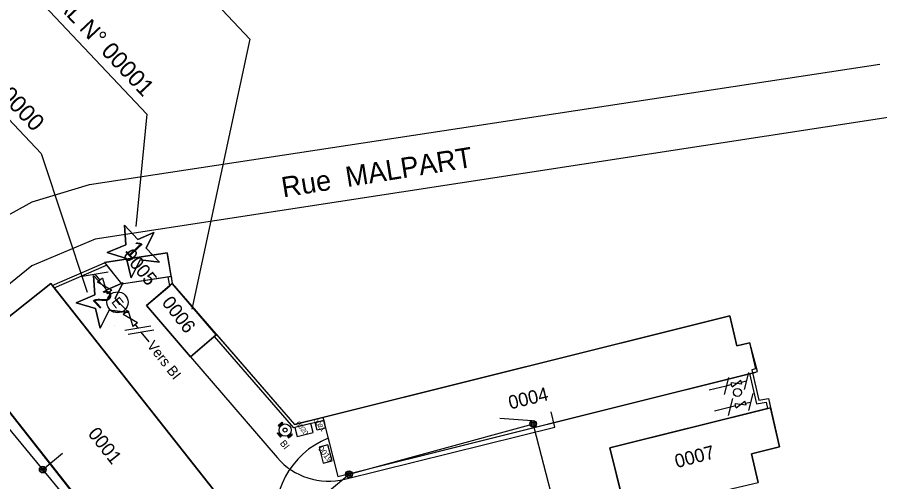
# Model space of a CAD drawing. Extents: x 703432 to 707394, y 7057985 to 7059523.
# Drawn here: x 704771.8 to 704899.3, y 7059327.9 to 7059396.7 of the extents above; entities that cross this region are included whole.
import ezdxf

# ---------------------------------------------------------------- set-up
doc = ezdxf.new("R2010")
doc.units = 0
for name, color, linetype in [('DH_HACHURE-MOTIF', 7, 'Continuous'), ('DH_TEXTE', 7, 'Continuous'), ('GEOSID_AIRE_AMENAGEE_NUMERO', 7, 'Continuous'), ('GEOSID_AIRE_AMENAGEE_POLYGONE', 7, 'Continuous'), ('GO_DALLE', 7, 'Continuous'), ('GO_MUR_EXTERIEUR', 7, 'Continuous'), ('IMM_LIMITE PHYSIQUE', 7, 'Continuous'), ('LIB_08', 7, 'Continuous'), ('R_PLU_CANALISATION_CL_A', 7, 'Continuous'), ('RES_BASSE TENSION AERIEN', 7, 'Continuous'), ('RES_CHAUFFAGE SECONDAIRE', 7, 'Continuous'), ('RES_EAU BASSE PRESSION', 7, 'Continuous'), ('RES_EAU BASSE PRESSION - EQUIP - TEXTE', 7, 'Continuous'), ('RES_INCENDIE - EQUIP - TEXTE', 7, 'Continuous'), ('SID_NUMERO_BATI', 7, 'Continuous'), ('SID_POLYLIGNES_BATI', 7, 'Continuous'), ('SID_POLYLIGNES_IMMEUBLE', 7, 'Continuous'), ('VOIRIE_ROUTE', 7, 'Continuous')]:
    doc.layers.add(name, color=color, linetype=linetype)

msp = doc.modelspace()

# ---------------------------------------------------------------- linework, layer by layer
at = {"layer": 'DH_HACHURE-MOTIF'}
for p, q in [((704790.92, 7059354), (704794.34, 7059356.93)), ((704794.34, 7059356.93), (704794.72, 7059357.25)), ((704794.72, 7059357.25), (704801.22, 7059349.66)), ((704797.42, 7059346.41), (704790.92, 7059354))]:
    msp.add_line(p, q, dxfattribs=at)
for points in [[(704794.09, 7059358.26), (704794.54, 7059358.33), (704793.96, 7059361.78), (704784.69, 7059360.35), (704785.02, 7059359.95), (704787.24, 7059357.23), (704794.09, 7059358.26)], [(704764.01, 7059346.61), (704766.21, 7059343.82), (704794.39, 7059308.1), (704800.87, 7059313.21), (704807.43, 7059318.38), (704806.81, 7059319.17), (704777.07, 7059356.86), (704776.77, 7059357.24), (704763.73, 7059346.96), (704764.01, 7059346.61)], [(704817.12, 7059337), (704817.4, 7059335.86), (704819.19, 7059328.7), (704880.85, 7059344.11), (704881.28, 7059344.22), (704880.13, 7059348.5), (704878.19, 7059348.01), (704877.16, 7059352.46), (704840.29, 7059343.25), (704817.01, 7059337.43), (704817.12, 7059337)], [(704801.22, 7059349.66), (704800.88, 7059349.36), (704797.42, 7059346.41)], [(704866.39, 7059325.41), (704866.63, 7059324.35), (704881.38, 7059327.83), (704880.38, 7059332.05), (704884.52, 7059333.08), (704883.19, 7059338.88), (704882.76, 7059338.77), (704859.41, 7059332.93), (704861.6, 7059324.2), (704866.39, 7059325.41)], [(704815.23, 7059336.52), (704812.85, 7059335.93), (704813.17, 7059334.64), (704815.55, 7059335.23), (704815.23, 7059336.52)], [(704817.06, 7059330.68), (704818.35, 7059331.01), (704817.75, 7059333.38), (704816.46, 7059333.06), (704817.06, 7059330.68)]]:
    msp.add_lwpolyline(points, dxfattribs=at)
at = {"layer": 'GEOSID_AIRE_AMENAGEE_POLYGONE'}
msp.add_lwpolyline([(704816.14, 7059335.54), (704815.86, 7059336.68), (704817.11, 7059337), (704817.4, 7059335.85)], close=True, dxfattribs=at)
at = {"layer": 'GO_DALLE'}
msp.add_lwpolyline([(704817.12, 7059337), (704817.4, 7059335.86), (704816.14, 7059335.54), (704815.86, 7059336.68)], close=True, dxfattribs=at)
at = {"layer": 'GO_MUR_EXTERIEUR'}
for p, q in [((704793.96, 7059361.78), (704784.69, 7059360.35)), ((704794.54, 7059358.33), (704793.96, 7059361.78)), ((704784.69, 7059360.35), (704787.24, 7059357.23)), ((704787.24, 7059357.23), (704794.54, 7059358.33)), ((704763.73, 7059346.96), (704776.77, 7059357.24)), ((704776.77, 7059357.24), (704807.43, 7059318.38)), ((704794.72, 7059357.25), (704790.92, 7059354)), ((704801.22, 7059349.66), (704794.72, 7059357.25)), ((704790.92, 7059354), (704797.42, 7059346.41)), ((704790.92, 7059354), (704790.92, 7059354)), ((704877.16, 7059352.46), (704817.01, 7059337.43)), ((704878.19, 7059348.01), (704877.16, 7059352.46)), ((704797.42, 7059346.41), (704801.22, 7059349.66)), ((704880.13, 7059348.5), (704878.19, 7059348.01)), ((704881.28, 7059344.22), (704880.13, 7059348.5)), ((704794.39, 7059308.1), (704763.73, 7059346.96)), ((704819.19, 7059328.7), (704881.28, 7059344.22)), ((704859.41, 7059332.93), (704883.19, 7059338.88)), ((704883.19, 7059338.88), (704884.52, 7059333.08)), ((704817.01, 7059337.43), (704819.19, 7059328.7)), ((704861.6, 7059324.2), (704859.41, 7059332.93)), ((704884.52, 7059333.08), (704880.38, 7059332.05)), ((704880.38, 7059332.05), (704881.38, 7059327.83))]:
    msp.add_line(p, q, dxfattribs=at)
for points in [[(704812.85, 7059335.93), (704813.17, 7059334.64), (704815.55, 7059335.23), (704815.23, 7059336.52)], [(704817.75, 7059333.38), (704816.46, 7059333.06), (704817.06, 7059330.68), (704818.35, 7059331.01)]]:
    msp.add_lwpolyline(points, close=True, dxfattribs=at)
at = {"layer": 'IMM_LIMITE PHYSIQUE'}
for p, q in [((704776.98, 7059356.98), (704784.71, 7059360.31)), ((704777.28, 7059356.62), (704785.02, 7059359.96)), ((704794.09, 7059358.26), (704794.32, 7059356.91)), ((704794.54, 7059358.33), (704794.72, 7059357.25)), ((704800.93, 7059349.41), (704812.67, 7059335.88)), ((704801.27, 7059349.7), (704812.82, 7059336.38)), ((704817.01, 7059337.43), (704812.82, 7059336.38)), ((704817.13, 7059337), (704812.67, 7059335.88)), ((704884.04, 7059333.58), (704884.04, 7059333.58))]:
    msp.add_line(p, q, dxfattribs=at)
for points in [[(704880.09, 7059343.93), (704881.14, 7059339.45), (704882.54, 7059339.72), (704882.75, 7059338.77)], [(704880.53, 7059344.03), (704881.48, 7059339.97), (704882.88, 7059340.24), (704883.19, 7059338.88)]]:
    msp.add_lwpolyline(points, dxfattribs=at)
at = {"layer": 'LIB_08'}
for p, q in [((704789.64, 7059363.78), (704787.67, 7059365.87)), ((704787.67, 7059365.87), (704787.84, 7059363)), ((704792.01, 7059364.8), (704789.64, 7059363.78)), ((704790.85, 7059362.5), (704792.01, 7059364.8)), ((704787.84, 7059363), (704785.12, 7059361.83)), ((704792.82, 7059360.41), (704790.85, 7059362.5)), ((704788.64, 7059358.1), (704789.97, 7059360.74)), ((704789.97, 7059360.74), (704792.82, 7059360.41)), ((704785.05, 7059356.34), (704783.08, 7059358.43)), ((704783.08, 7059358.43), (704783.25, 7059355.57)), ((704787.41, 7059357.36), (704785.05, 7059356.34)), ((704786.26, 7059355.06), (704787.41, 7059357.36)), ((704783.25, 7059355.57), (704780.53, 7059354.39)), ((704788.23, 7059352.97), (704786.26, 7059355.06)), ((704784.05, 7059350.66), (704785.38, 7059353.31)), ((704785.38, 7059353.31), (704788.23, 7059352.97))]:
    msp.add_line(p, q, dxfattribs=at)
for points in [[(704767.68, 7059434.23), (704806.21, 7059393.39), (704797.62, 7059353.45)], [(704752.82, 7059422.73), (704790.94, 7059382.33), (704789.35, 7059365.71)], [(704733.91, 7059420.43), (704775.36, 7059376.5), (704782.12, 7059355.95)], [(704785.12, 7059361.83), (704787.96, 7059360.98), (704787.96, 7059360.98)], [(704787.96, 7059360.98), (704787.96, 7059360.98), (704788.64, 7059358.1)], [(704780.53, 7059354.39), (704783.36, 7059353.54), (704783.37, 7059353.54)], [(704783.37, 7059353.54), (704783.36, 7059353.54), (704784.05, 7059350.66)]]:
    msp.add_lwpolyline(points, dxfattribs=at)
for points in [[(704787.67, 7059365.87), (704789.65, 7059363.78), (704792.01, 7059364.8), (704790.85, 7059362.5), (704792.82, 7059360.41), (704789.97, 7059360.74), (704788.64, 7059358.1), (704787.96, 7059360.98), (704785.12, 7059361.83), (704787.84, 7059363)], [(704783.08, 7059358.43), (704785.05, 7059356.34), (704787.41, 7059357.36), (704786.26, 7059355.06), (704788.23, 7059352.97), (704785.38, 7059353.31), (704784.05, 7059350.66), (704783.36, 7059353.54), (704780.53, 7059354.39), (704783.25, 7059355.57)]]:
    msp.add_lwpolyline(points, close=True, dxfattribs=at)
at = {"layer": 'R_PLU_CANALISATION_CL_A'}
msp.add_circle((704878.3, 7059341.14), 0.6, dxfattribs=at)
at = {"layer": 'RES_BASSE TENSION AERIEN'}
msp.add_line((704797.42, 7059346.41), (704810.24, 7059331.49), dxfattribs=at)
msp.add_lwpolyline([(704820.24, 7059328.3), (704851.28, 7059336.02), (704850.74, 7059338.26)], dxfattribs=at)
msp.add_arc((704817.83, 7059338.01), 10, 220.6803, 283.9557, dxfattribs=at)
at = {"layer": 'RES_CHAUFFAGE SECONDAIRE'}
msp.add_arc((704822.5, 7059322.74), 12.55, 112.1042, 191.7308, dxfattribs=at)
at = {"layer": 'RES_EAU BASSE PRESSION'}
for p, q in [((704762.6, 7059345.41), (704794.07, 7059307.33)), ((704879.94, 7059344.09), (704879.3, 7059341.58)), ((704877.42, 7059342.29), (704876.65, 7059342.09)), ((704880.56, 7059340.98), (704879.92, 7059338.47)), ((704878.04, 7059339.17), (704877.26, 7059338.98)), ((704843.14, 7059337.32), (704847.96, 7059336.97)), ((704820.86, 7059329.03), (704847.6, 7059336.36)), ((704848.21, 7059336.01), (704855.35, 7059308.06)), ((704775.57, 7059329.72), (704778.49, 7059332.13)), ((704811.85, 7059321.58), (704820.86, 7059329.03))]:
    msp.add_line(p, q, dxfattribs=at)
at = {"layer": 'RES_EAU BASSE PRESSION - EQUIP - TEXTE'}
for p, q in [((704877.5, 7059341.99), (704877.35, 7059342.58)), ((704878.95, 7059342.36), (704877.35, 7059342.58)), ((704877.5, 7059341.99), (704878.81, 7059342.94)), ((704878.95, 7059342.36), (704878.81, 7059342.94)), ((704878.88, 7059342.65), (704879.62, 7059342.84)), ((704876.65, 7059342.09), (704874.12, 7059341.46)), ((704877.26, 7059338.98), (704874.89, 7059338.38)), ((704878.11, 7059338.88), (704877.97, 7059339.46)), ((704879.57, 7059339.24), (704877.97, 7059339.46)), ((704878.11, 7059338.88), (704879.42, 7059339.83)), ((704879.57, 7059339.24), (704879.42, 7059339.83)), ((704879.49, 7059339.54), (704880.24, 7059339.72))]:
    msp.add_line(p, q, dxfattribs=at)
for centre, radius in [((704848.09, 7059336.49), 0.5), ((704848.09, 7059336.49), 0.45), ((704848.09, 7059336.49), 0.25), ((704848.09, 7059336.49), 0.05), ((704775.57, 7059329.72), 0.5), ((704775.57, 7059329.72), 0.45), ((704775.57, 7059329.72), 0.25), ((704775.57, 7059329.72), 0.05), ((704820.86, 7059329.03), 0.5), ((704820.86, 7059329.03), 0.45), ((704820.86, 7059329.03), 0.25), ((704820.86, 7059329.03), 0.05)]:
    msp.add_circle(centre, radius, dxfattribs=at)
at = {"layer": 'RES_INCENDIE - EQUIP - TEXTE'}
for p, q in [((704781.41, 7059358.32), (704785.23, 7059358.99)), ((704784.04, 7059357.75), (704783.32, 7059358.66)), ((704784.39, 7059358.03), (704783.68, 7059357.47)), ((704784.39, 7059358.03), (704785.08, 7059355.71)), ((704785.78, 7059356.26), (704783.68, 7059357.47)), ((704785.78, 7059356.26), (704785.08, 7059355.71)), ((704785.43, 7059355.99), (704785.66, 7059355.69)), ((704788.18, 7059353.23), (704787.47, 7059352.67)), ((704789.57, 7059351.46), (704787.47, 7059352.67)), ((704787.83, 7059352.95), (704787.59, 7059353.24)), ((704788.18, 7059353.23), (704788.87, 7059350.9)), ((704789.57, 7059351.46), (704788.87, 7059350.9)), ((704786.11, 7059351.04), (704786.11, 7059351.04)), ((704787.72, 7059350.33), (704791.54, 7059351)), ((704788.18, 7059349.74), (704792, 7059350.42)), ((704789.22, 7059351.18), (704789.63, 7059350.67)), ((704790.09, 7059350.08), (704791.25, 7059348.61)), ((704876.96, 7059343.35), (704876.33, 7059340.84)), ((704877.58, 7059340.23), (704876.95, 7059337.72)), ((704810.38, 7059336.27), (704810.93, 7059336.73)), ((704810.38, 7059336.27), (704810.47, 7059336.16)), ((704810.47, 7059336.16), (704811.03, 7059336.61)), ((704810.52, 7059336.19), (704810.65, 7059336.04)), ((704810.93, 7059336.73), (704811.03, 7059336.61)), ((704810.98, 7059336.57), (704811.11, 7059336.42)), ((704810.26, 7059335.09), (704810.37, 7059335.18)), ((704810.26, 7059335.09), (704810.71, 7059334.53)), ((704810.37, 7059335.18), (704810.83, 7059334.63)), ((704810.41, 7059335.14), (704810.57, 7059335.27)), ((704810.79, 7059334.67), (704810.95, 7059334.8)), ((704811.8, 7059334.53), (704812.36, 7059334.99)), ((704811.9, 7059334.42), (704812.45, 7059334.87)), ((704812.18, 7059335.11), (704812.31, 7059334.95)), ((704812.36, 7059334.99), (704812.45, 7059334.87)), ((704810.71, 7059334.53), (704810.83, 7059334.63)), ((704811.72, 7059334.73), (704811.85, 7059334.57)), ((704811.8, 7059334.53), (704811.9, 7059334.42))]:
    msp.add_line(p, q, dxfattribs=at)
for centre, radius in [((704786.63, 7059354.47), 1.56), ((704811.41, 7059335.57), 0.9), ((704811.41, 7059335.57), 0.3)]:
    msp.add_circle(centre, radius, dxfattribs=at)
at = {"layer": 'SID_POLYLIGNES_BATI'}
for p, q in [((704793.96, 7059361.78), (704784.69, 7059360.35)), ((704794.54, 7059358.33), (704793.96, 7059361.78)), ((704784.69, 7059360.35), (704787.24, 7059357.23)), ((704787.24, 7059357.23), (704794.54, 7059358.33)), ((704763.73, 7059346.96), (704776.77, 7059357.24)), ((704776.77, 7059357.24), (704807.43, 7059318.38)), ((704794.72, 7059357.25), (704790.92, 7059354)), ((704801.22, 7059349.66), (704794.72, 7059357.25)), ((704790.92, 7059354), (704797.42, 7059346.41)), ((704790.92, 7059354), (704790.92, 7059354)), ((704877.16, 7059352.46), (704817.01, 7059337.43)), ((704878.19, 7059348.01), (704877.16, 7059352.46)), ((704797.42, 7059346.41), (704801.22, 7059349.66)), ((704880.13, 7059348.5), (704878.19, 7059348.01)), ((704881.28, 7059344.22), (704880.13, 7059348.5)), ((704794.39, 7059308.1), (704763.73, 7059346.96)), ((704819.19, 7059328.7), (704881.28, 7059344.22)), ((704817.01, 7059337.43), (704819.19, 7059328.7))]:
    msp.add_line(p, q, dxfattribs=at)
for points in [[(704812.85, 7059335.93), (704813.17, 7059334.64), (704815.55, 7059335.23), (704815.23, 7059336.52)], [(704816.14, 7059335.54), (704815.86, 7059336.68), (704817.12, 7059337), (704817.4, 7059335.86)], [(704817.75, 7059333.38), (704816.46, 7059333.06), (704817.06, 7059330.68), (704818.35, 7059331.01)]]:
    msp.add_lwpolyline(points, close=True, dxfattribs=at)
at = {"layer": 'SID_POLYLIGNES_IMMEUBLE'}
for p, q in [((704812.82, 7059336.38), (704877.16, 7059352.46)), ((704877.16, 7059352.46), (704878.19, 7059348.01)), ((704878.19, 7059348.01), (704880.09, 7059348.49)), ((704812.82, 7059336.38), (704812.82, 7059336.38)), ((704884.52, 7059333.08), (704880.38, 7059332.05)), ((704880.38, 7059332.05), (704881.38, 7059327.83))]:
    msp.add_line(p, q, dxfattribs=at)
for points in [[(704776.77, 7059357.24), (704776.98, 7059356.98), (704784.71, 7059360.31), (704784.69, 7059360.35), (704793.96, 7059361.78)], [(704793.96, 7059361.78), (704794.72, 7059357.25), (704812.82, 7059336.38)], [(704748.31, 7059333.98), (704763.73, 7059346.96), (704776.77, 7059357.24)], [(704880.09, 7059348.49), (704880.99, 7059344.65), (704880.42, 7059344.5), (704881.48, 7059339.97), (704882.88, 7059340.24), (704884.52, 7059333.08)]]:
    msp.add_lwpolyline(points, dxfattribs=at)
at = {"layer": 'VOIRIE_ROUTE'}
for points in [[(704740.74, 7059343.69), (704767.97, 7059366.05), (704774, 7059369.35), (704782.46, 7059371.89), (704899.35, 7059389.72)], [(704900.6, 7059381.84), (704783.31, 7059363.81), (704773.95, 7059359.85), (704746.36, 7059337.47)]]:
    msp.add_lwpolyline(points, dxfattribs=at)

# ---------------------------------------------------------------- texts
at = {"layer": 'DH_TEXTE'}
msp.add_text('Rue  MALPART', height=3, rotation=9.1668, dxfattribs=at).set_placement((704811.13, 7059369.98))
at = {"layer": 'GEOSID_AIRE_AMENAGEE_NUMERO'}
msp.add_text('0021', height=0.225, rotation=8.0308, dxfattribs=at).set_placement((704816.22, 7059336.18))
at = {"layer": 'LIB_08'}
for s, height, rotation, p in [('30000110341129_LOCAL N° 00001', 2.5, 313.3307, (704753.56, 7059423.84)), ('40626.548.0730.05_N° LOCAL 00000', 2.5, 313.9654, (704735, 7059420.29)), ('1', 2.65, 313.3307, (704787.59, 7059362.09)), ('2', 2.65, 313.3307, (704782.83, 7059354.83))]:
    msp.add_text(s, height=height, rotation=rotation, dxfattribs=at).set_placement(p)
at = {"layer": 'RES_EAU BASSE PRESSION - EQUIP - TEXTE'}
msp.add_text('Vers réseau eau', height=1.5, rotation=308.2727, dxfattribs=at).set_placement((704763.94, 7059330.84))
at = {"layer": 'RES_INCENDIE - EQUIP - TEXTE'}
for s, height, p in [('E', 1.5, (704785.64, 7059354.51)), ('Vers BI', 1.5, (704790.9, 7059348.05)), ('BI', 1, (704810.58, 7059333.6))]:
    msp.add_text(s, height=height, rotation=308.2727, dxfattribs=at).set_placement(p)
at = {"layer": 'SID_NUMERO_BATI'}
for s, height, rotation, p in [('0005', 2, 309.3307, (704787.32, 7059361.37)), ('0006', 2, 307.9879, (704793.08, 7059354.4)), ('0004', 2, 13.5243, (704844.7, 7059338.62)), ('0021', 0.702, 308.0308, (704815.55, 7059336.98)), ('0020', 0.738, 308.0308, (704812.94, 7059336.52)), ('0001', 2, 308.2727, (704782.15, 7059335)), ('0019', 0.866, 308.0308, (704816.24, 7059332.77)), ('0007', 2, 14.5051, (704869.32, 7059329.93))]:
    msp.add_text(s, height=height, rotation=rotation, dxfattribs=at).set_placement(p)

doc.saveas('drawing.dxf')
